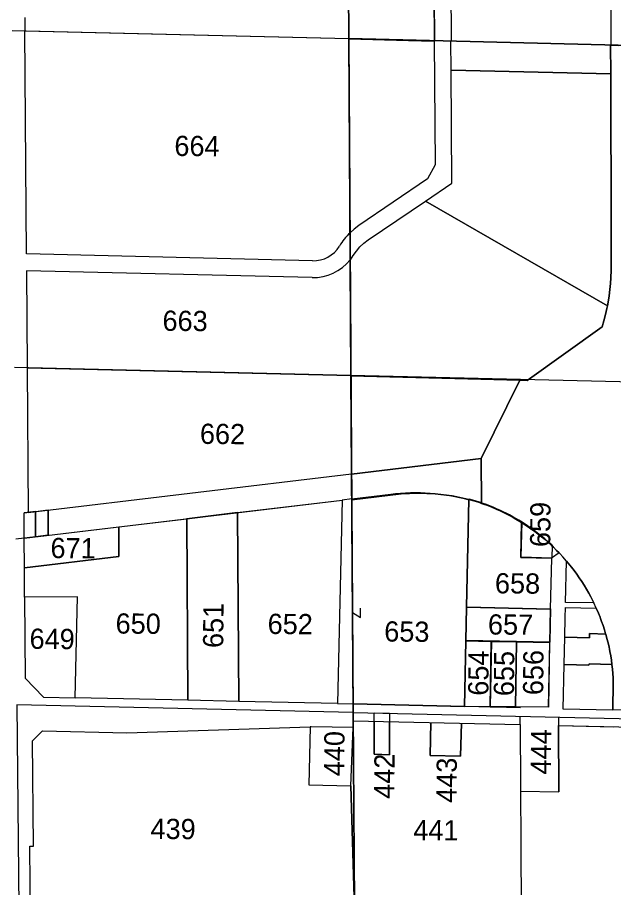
# Model space of a CAD drawing. Extents: x 582596 to 627039, y 145946 to 197316.
# Drawn here: x 604584 to 606930, y 174808 to 178233 of the extents above; entities that cross this region are included whole.
import ezdxf

# ---------------------------------------------------------------- set-up
doc = ezdxf.new("R2010")
doc.units = 0
for name, color, linetype in [('Defpoints 2', 7, 'Continuous'), ('E_RW_Existing', 7, 'Continuous'), ('E_RW_SixteenthLine', 7, 'Continuous'), ('P_MISC_NoPlot', 7, 'Continuous'), ('P_RW_PropertyConnector', 7, 'Continuous'), ('P_RW_PropertyLine', 7, 'Continuous'), ('P_RW_QuarterLine', 7, 'Continuous'), ('P_RW_SectionLine', 7, 'Continuous'), ('ROW', 7, 'Continuous')]:
    doc.layers.add(name, color=color, linetype=linetype)

msp = doc.modelspace()

# ---------------------------------------------------------------- linework, layer by layer
at = {"layer": 'E_RW_Existing'}
for p, q in [((606221.3, 178682.7), (606225.2, 178141.3)), ((605893.3, 177278.2), (605892.6, 177385)), ((605449.8, 176283.3), (605250, 176259.4))]:
    msp.add_line(p, q, dxfattribs=at)
at = {"layer": 'E_RW_SixteenthLine'}
for p, q in [((605887.7, 178149.4), (605904.6, 175497.2)), ((605896.2, 176823.3), (604572.4, 176854.1)), ((607220, 176792.5), (605896.2, 176823.3)), ((605904.6, 175497.2), (605923.5, 172850.3))]:
    msp.add_line(p, q, dxfattribs=at)
at = {"layer": 'P_MISC_NoPlot'}
for points in [[(606993.6, 160308.3), (600102.2, 147849.8), (582596.4, 147849.8), (584141, 197316), (605971.8, 196079.3), (609781.9, 181857.8), (607212.6, 178117.5), (605887.7, 178149.4), (605896.2, 176823.3), (605904.6, 175497.2), (605914.1, 174173.8), (605923.5, 172850.3), (605943, 171523.9), (604673.2, 170334), (604629.1, 170230.1), (604629.4, 170060), (605962, 170045), (605958.9, 168865.5), (605954.8, 167533.5), (604633.8, 167557.8), (604638.5, 164918.1), (606975.2, 164878.2), (606986.2, 162297)], [(606993.6, 160308.3), (600102.2, 147849.8), (582596.4, 147849.8), (584141, 197316), (605971.8, 196079.3), (609781.9, 181857.8), (607212.6, 178117.5), (605887.7, 178149.4), (605896.2, 176823.3), (605904.6, 175497.2), (605914.1, 174173.8), (605923.5, 172850.3), (605943, 171523.9), (604673.2, 170334), (604629.1, 170230.1), (604629.4, 170060), (605962, 170045), (605958.9, 168865.5), (605954.8, 167533.5), (604633.8, 167557.8), (604638.5, 164918.1), (606975.2, 164878.2), (606986.2, 162297)], [(606993.6, 160308.3), (600102.2, 147849.8), (582596.4, 147849.8), (584141, 197316), (605971.8, 196079.3), (609781.9, 181857.8), (607212.6, 178117.5), (605887.7, 178149.4), (605896.2, 176823.3), (605904.6, 175497.2), (605914.1, 174173.8), (605923.5, 172850.3), (605943, 171523.9), (604673.2, 170334), (604629.1, 170230.1), (604629.4, 170060), (605962, 170045), (605958.9, 168865.5), (605954.8, 167533.5), (604633.8, 167557.8), (604638.5, 164918.1), (606975.2, 164878.2), (606986.2, 162297)], [(606996.1, 159645.4), (606986.2, 162297), (606975.2, 164878.2), (604638.5, 164918.1), (604633.8, 167557.8), (605954.8, 167533.5), (605962, 170045), (604629.4, 170060), (604629.1, 170230.1), (604673.2, 170334), (605943, 171523.9), (605923.5, 172850.3), (605914.1, 174173.8), (605904.6, 175497.2), (605896.2, 176823.3), (605887.7, 178149.4), (607212.6, 178117.5), (607212.6, 178117.5), (627039.4, 170600.9), (626501.4, 158385.8), (609890.9, 158385.8), (607772.6, 159126.1)]]:
    msp.add_lwpolyline(points, close=True, dxfattribs=at)
at = {"layer": 'P_RW_PropertyConnector'}
for p, q in [((605902.1, 175890.3), (605934.3, 175871.1)), ((605904.4, 175889), (605904.4, 175889)), ((605934.3, 175871.1), (605934.3, 175906.8))]:
    msp.add_line(p, q, dxfattribs=at)
at = {"layer": 'P_RW_PropertyLine'}
for p, q in [((605887.7, 178147.9), (606123.4, 178142.3)), ((606123.4, 178142.3), (605887.7, 178147.9)), ((606123.4, 178142.3), (606223.7, 178139.8)), ((606223.7, 178139.8), (606123.4, 178142.3)), ((606223.7, 178141.3), (606223.7, 178139.8)), ((606223.7, 178139.8), (606227.2, 177653)), ((606223.7, 178139.8), (606223.7, 178139.8)), ((606286.8, 178138.3), (606286.8, 178139.8)), ((606289.3, 178138.3), (606286.8, 178138.3)), ((606290.1, 178025.1), (606289.3, 178138.3)), ((606917.6, 178124.6), (606917.6, 178123.1)), ((606917.6, 178123.1), (606917.6, 178124.6)), ((606917.6, 178123.1), (606918, 178123.1)), ((606918, 178123.1), (606917.6, 178123.1)), ((606918, 178123.1), (606918, 178123.1)), ((606918, 178123.1), (606918.5, 178010)), ((606947.5, 178122.4), (606918, 178123.1)), ((606918.5, 178010), (606918, 178123.1)), ((606918, 178123.1), (606918, 178123.1)), ((606918, 178123.1), (606947.5, 178122.4)), ((606918.5, 178010), (606290.1, 178025.1)), ((606293.4, 177580.4), (606290.1, 178025.1)), ((606290.1, 178025.1), (606918.5, 178010)), ((606918.5, 178010), (606920.9, 177374.7)), ((606920.9, 177374.7), (606918.5, 178010)), ((606227.2, 177653), (606197.9, 177597.1)), ((606197.9, 177597.1), (605927.6, 177413.4)), ((606189.2, 177509.7), (606293.4, 177580.4)), ((605964.3, 177356.9), (606189.2, 177509.7)), ((606905.4, 177097.4), (606189.2, 177509.7)), ((606189.2, 177509.7), (606905.4, 177097.4)), ((605908.7, 177399.4), (605892.6, 177385)), ((605927.6, 177413.4), (605908.7, 177399.4)), ((606920.9, 177374.7), (606919.9, 177235.7)), ((606919.9, 177235.7), (606920.9, 177374.7)), ((605917.6, 177312.7), (605931.6, 177329.1)), ((605931.6, 177329.1), (605947.2, 177343.9)), ((605947.2, 177343.9), (605964.3, 177356.9)), ((605894.3, 177278.4), (605905.5, 177294.9)), ((605905.5, 177294.9), (605917.6, 177312.7)), ((605893.3, 177277.7), (605894.3, 177278.4)), ((606919.9, 177235.7), (606919.1, 177210.8)), ((606919.1, 177210.8), (606919.9, 177235.7)), ((605743.6, 177208.6), (605743.6, 177208.6)), ((606918.9, 177208.2), (606917.6, 177185.9)), ((606917.6, 177185.9), (606918.9, 177208.2)), ((606919.1, 177210.8), (606918.9, 177208.2)), ((606918.9, 177208.2), (606919.1, 177210.8)), ((606915.2, 177161.1), (606912.1, 177136.4)), ((606912.1, 177136.4), (606915.2, 177161.1)), ((606917.6, 177185.9), (606915.2, 177161.1)), ((606915.2, 177161.1), (606917.6, 177185.9)), ((606912.1, 177136.4), (606908.2, 177111.7)), ((606908.2, 177111.7), (606912.1, 177136.4)), ((606903.4, 177087.3), (606897.9, 177062.9)), ((606897.9, 177062.9), (606903.4, 177087.3)), ((606905.4, 177097.4), (606903.4, 177087.3)), ((606903.4, 177087.3), (606905.4, 177097.4)), ((606908.2, 177111.7), (606905.4, 177097.4)), ((606905.4, 177097.4), (606908.2, 177111.7)), ((606897.9, 177062.9), (606891.7, 177038.8)), ((606891.7, 177038.8), (606897.9, 177062.9)), ((606891.7, 177038.8), (606884.6, 177014.9)), ((606884.6, 177014.9), (606891.7, 177038.8)), ((606884.6, 177014.9), (606589.4, 176803.8)), ((606589.4, 176803.8), (606884.6, 177014.9)), ((604622.4, 176852.9), (604626.5, 176284.4)), ((606560.5, 176804.5), (605896.2, 176821.9)), ((605896.2, 176821.9), (606560.5, 176804.5)), ((606560.5, 176804.5), (606408.8, 176496.3)), ((606408.8, 176496.3), (606560.5, 176804.5)), ((606589.4, 176803.8), (606560.5, 176804.5)), ((606560.5, 176804.5), (606589.4, 176803.8)), ((606408.8, 176496.3), (605898.7, 176435)), ((605898.7, 176435), (606408.8, 176496.3)), ((606410, 176320), (606408.8, 176496.3)), ((606408.8, 176496.3), (606410, 176320)), ((606093.9, 176357.2), (605899.3, 176333.9)), ((605899.3, 176333.9), (606093.9, 176357.2)), ((606052.7, 176355.4), (605899.3, 176337)), ((606160.9, 176360.5), (606093.9, 176357.2)), ((606093.9, 176357.2), (606160.9, 176360.5)), ((606228, 176357.9), (606160.9, 176360.5)), ((606160.9, 176360.5), (606228, 176357.9)), ((606294.5, 176349.5), (606228, 176357.9)), ((606228, 176357.9), (606294.5, 176349.5)), ((606360.1, 176335.3), (606294.5, 176349.5)), ((606294.5, 176349.5), (606360.1, 176335.3)), ((606360.1, 176335.3), (606350.7, 175911.1)), ((606350.7, 175911.1), (606360.1, 176335.3)), ((606385.3, 176328.1), (606360.1, 176335.3)), ((606360.1, 176335.3), (606385.3, 176328.1)), ((606402, 176322.7), (606385.3, 176328.1)), ((606385.3, 176328.1), (606402, 176322.7)), ((606410, 176320), (606402, 176322.7)), ((606402, 176322.7), (606410, 176320)), ((606418.6, 176317), (606410, 176320)), ((606410, 176320), (606418.6, 176317)), ((606435.1, 176310.9), (606418.6, 176317)), ((606418.6, 176317), (606435.1, 176310.9)), ((606451.4, 176304.5), (606435.1, 176310.9)), ((606435.1, 176310.9), (606451.4, 176304.5)), ((606467.5, 176297.7), (606451.4, 176304.5)), ((606451.4, 176304.5), (606467.5, 176297.7)), ((606483.5, 176290.5), (606467.5, 176297.7)), ((606467.5, 176297.7), (606483.5, 176290.5)), ((604654.4, 176287.8), (604609.5, 176282.4)), ((604610.2, 176182.8), (604609.5, 176282.4)), ((604655.1, 176188.2), (604654.4, 176287.8)), ((604705.1, 176194.1), (604704.4, 176293.8)), ((606499.3, 176282.9), (606483.5, 176290.5)), ((606483.5, 176290.5), (606499.3, 176282.9)), ((606515, 176275), (606499.3, 176282.9)), ((606499.3, 176282.9), (606515, 176275)), ((606530.5, 176266.7), (606515, 176275)), ((606515, 176275), (606530.5, 176266.7)), ((606545.7, 176258.1), (606530.5, 176266.7)), ((606530.5, 176266.7), (606545.7, 176258.1)), ((606568.1, 176244.5), (606545.7, 176258.1)), ((606545.7, 176258.1), (606568.1, 176244.5)), ((606568.1, 176244.5), (606565.1, 176106.3)), ((606565.1, 176106.3), (606568.1, 176244.5)), ((606590.3, 176230.2), (606568.1, 176244.5)), ((606568.1, 176244.5), (606590.3, 176230.2)), ((606604.7, 176220.2), (606590.3, 176230.2)), ((606590.3, 176230.2), (606604.7, 176220.2)), ((606618.9, 176209.9), (606604.7, 176220.2)), ((606604.7, 176220.2), (606618.9, 176209.9)), ((606632.9, 176199.3), (606618.9, 176209.9)), ((606618.9, 176209.9), (606632.9, 176199.3)), ((606646.6, 176188.3), (606632.9, 176199.3)), ((606632.9, 176199.3), (606646.6, 176188.3)), ((604610.2, 176182.8), (604577.2, 176178.8)), ((604655.1, 176188.2), (604610.2, 176182.8)), ((606660.1, 176177.1), (606646.6, 176188.3)), ((606646.6, 176188.3), (606660.1, 176177.1)), ((606673.3, 176165.5), (606660.1, 176177.1)), ((606660.1, 176177.1), (606673.3, 176165.5)), ((606686.2, 176153.5), (606673.3, 176165.5)), ((606673.3, 176165.5), (606686.2, 176153.5)), ((606715.5, 176124.6), (606685.1, 176103.7)), ((606693.3, 176147), (606686.2, 176153.5)), ((606686.2, 176153.5), (606693.3, 176147)), ((606687.7, 176154.8), (606686.6, 176104.8)), ((606705.7, 176134.7), (606693.3, 176147)), ((606693.3, 176147), (606705.7, 176134.7)), ((606715.5, 176124.6), (606705.7, 176134.7)), ((606705.7, 176134.7), (606715.5, 176124.6)), ((606718, 176122.1), (606715.5, 176124.6)), ((606565.1, 176106.3), (606685.1, 176103.7)), ((606685.1, 176103.7), (606565.1, 176106.3)), ((606685.1, 176103.7), (606680.6, 175903.7)), ((606729.9, 176109.2), (606718, 176122.1)), ((606744.9, 176092.2), (606729.9, 176109.2)), ((606741.3, 175930.3), (606744.9, 176092.2)), ((606763.9, 176069.1), (606744.9, 176092.2)), ((606744.9, 176092.2), (606763.9, 176069.1)), ((604611.8, 175950.8), (604611, 176065.8)), ((606774.6, 176055.2), (606763.9, 176069.1)), ((606763.9, 176069.1), (606774.6, 176055.2)), ((606785, 176041.1), (606774.6, 176055.2)), ((606774.6, 176055.2), (606785, 176041.1)), ((606795, 176026.7), (606785, 176041.1)), ((606785, 176041.1), (606795, 176026.7)), ((606804.8, 176012.1), (606795, 176026.7)), ((606795, 176026.7), (606804.8, 176012.1)), ((606814.1, 175997.3), (606804.8, 176012.1)), ((606804.8, 176012.1), (606814.1, 175997.3)), ((606823.2, 175982.3), (606814.1, 175997.3)), ((606814.1, 175997.3), (606823.2, 175982.3)), ((606831.9, 175967), (606823.2, 175982.3)), ((606823.2, 175982.3), (606831.9, 175967)), ((606840.3, 175951.6), (606831.9, 175967)), ((606831.9, 175967), (606840.3, 175951.6)), ((606852.2, 175927.9), (606741.3, 175930.3)), ((606852.2, 175927.9), (606840.3, 175951.6)), ((606840.3, 175951.6), (606852.2, 175927.9)), ((606861.7, 175907.7), (606852.2, 175927.9)), ((606350.7, 175911.1), (606347.8, 175779.1)), ((606347.8, 175779.1), (606350.7, 175911.1)), ((606350.7, 175911.1), (606680.6, 175903.7)), ((606680.6, 175903.7), (606350.7, 175911.1)), ((606680.6, 175903.7), (606677.7, 175771.7)), ((606739.9, 175870.4), (606740.8, 175910.3)), ((606740.8, 175910.3), (606861.7, 175907.7)), ((606870.1, 175888.2), (606861.7, 175907.7)), ((606861.7, 175907.7), (606870.1, 175888.2)), ((606876.7, 175871.9), (606870.1, 175888.2)), ((606870.1, 175888.2), (606876.7, 175871.9)), ((606738.2, 175793.4), (606739.9, 175870.4)), ((606878.4, 175867.3), (606876.7, 175871.9)), ((606876.7, 175871.9), (606878.4, 175867.3)), ((606882.9, 175855.5), (606878.4, 175867.3)), ((606878.4, 175867.3), (606882.9, 175855.5)), ((606888.7, 175838.9), (606882.9, 175855.5)), ((606882.9, 175855.5), (606888.7, 175838.9)), ((606894.1, 175822.3), (606888.7, 175838.9)), ((606888.7, 175838.9), (606894.1, 175822.3)), ((606898.7, 175806.8), (606894.1, 175822.3)), ((606894.1, 175822.3), (606898.7, 175806.8)), ((606735.8, 175685.4), (606738.2, 175793.4)), ((606835.4, 175791.2), (606738.2, 175793.4)), ((606738.2, 175793.4), (606835.4, 175791.2)), ((606835.8, 175808.2), (606835.4, 175791.2)), ((606835.4, 175791.2), (606835.8, 175808.2)), ((606899.1, 175805.5), (606835.8, 175808.2)), ((606835.8, 175808.2), (606899.1, 175805.5)), ((606899.1, 175805.5), (606898.7, 175806.8)), ((606898.7, 175806.8), (606899.1, 175805.5)), ((606903.8, 175788.6), (606899.1, 175805.5)), ((606899.1, 175805.5), (606903.8, 175788.6)), ((606908.1, 175771.5), (606903.8, 175788.6)), ((606903.8, 175788.6), (606908.1, 175771.5)), ((606347.8, 175779.1), (606343.6, 175520.3)), ((606343.6, 175520.3), (606347.8, 175779.1)), ((606347.8, 175779.1), (606447.9, 175776.8)), ((606447.9, 175776.8), (606347.8, 175779.1)), ((606447.9, 175776.8), (606443.6, 175519.6)), ((606443.6, 175519.6), (606447.9, 175776.8)), ((606447.9, 175776.8), (606547.8, 175774.6)), ((606547.8, 175774.6), (606447.9, 175776.8)), ((606547.8, 175774.6), (606543.6, 175518.9)), ((606543.6, 175518.9), (606547.8, 175774.6)), ((606547.8, 175774.6), (606677.7, 175771.7)), ((606677.7, 175771.7), (606547.8, 175774.6)), ((606673.6, 175517.9), (606679.3, 175772.9)), ((606677.7, 175771.7), (606673.6, 175517.9)), ((606912, 175754.4), (606908.1, 175771.5)), ((606908.1, 175771.5), (606912, 175754.4)), ((606913.6, 175746.4), (606912, 175754.4)), ((606912, 175754.4), (606913.6, 175746.4)), ((606915.4, 175737.3), (606913.6, 175746.4)), ((606913.6, 175746.4), (606915.4, 175737.3)), ((606918.6, 175720), (606915.4, 175737.3)), ((606915.4, 175737.3), (606918.6, 175720)), ((606921.3, 175702.7), (606918.6, 175720)), ((606918.6, 175720), (606921.3, 175702.7)), ((606732, 175510.4), (606735.8, 175685.4)), ((606833.1, 175683.2), (606735.8, 175685.4)), ((606735.8, 175685.4), (606833.1, 175683.2)), ((606833.2, 175688.2), (606833.1, 175683.2)), ((606833.1, 175683.2), (606833.2, 175688.2)), ((606923.5, 175686.2), (606833.2, 175688.2)), ((606833.2, 175688.2), (606923.5, 175686.2)), ((606923.5, 175686.2), (606921.3, 175702.7)), ((606921.3, 175702.7), (606923.5, 175686.2)), ((606923.6, 175685.3), (606923.5, 175686.2)), ((606923.5, 175686.2), (606923.6, 175685.3)), ((606925.5, 175667.8), (606923.6, 175685.3)), ((606923.6, 175685.3), (606925.5, 175667.8)), ((606927, 175650.4), (606925.5, 175667.8)), ((606925.5, 175667.8), (606927, 175650.4)), ((606928.1, 175632.9), (606927, 175650.4)), ((606927, 175650.4), (606928.1, 175632.9)), ((606926.4, 175506.1), (606928.8, 175615.3)), ((606928.8, 175615.3), (606926.4, 175506.1)), ((606928.4, 175626.1), (606928.1, 175632.9)), ((606928.1, 175632.9), (606928.4, 175626.1)), ((606928.8, 175615.3), (606928.4, 175626.1)), ((606928.4, 175626.1), (606928.8, 175615.3)), ((606563.5, 175515.4), (605904.4, 175530.2)), ((606343.6, 175520.3), (605904.4, 175530.2)), ((606443.6, 175519.6), (606343.6, 175520.3)), ((606673.6, 175517.9), (606343.6, 175520.3)), ((606543.6, 175518.9), (606443.6, 175519.6)), ((606673.6, 175517.9), (606543.6, 175518.9)), ((606926.4, 175506.1), (606732, 175510.4)), ((607029.2, 175508.8), (606926.4, 175506.1)), ((605987.5, 175462.3), (605987.4, 175495.3)), ((605987.4, 175495.3), (606047.4, 175494)), ((606047.4, 175494), (606047.5, 175461)), ((606562.7, 175449.4), (606562.5, 175482.4)), ((606712.5, 175479.1), (606712.7, 175446)), ((605904.9, 175464.2), (606562, 175449.4)), ((605987.7, 175332.1), (605987.5, 175462.3)), ((605987.5, 175462.3), (605987.7, 175332.1)), ((606047.5, 175461), (606047.7, 175330.7)), ((606047.7, 175330.7), (606047.5, 175461)), ((606207.9, 175327.3), (606210.8, 175457.3)), ((606210.8, 175457.3), (606207.9, 175327.3)), ((606330.8, 175454.6), (606327.9, 175324.6)), ((606327.9, 175324.6), (606330.8, 175454.6)), ((606562.7, 175449.4), (606566.4, 174710)), ((606712.7, 175446), (606931.2, 175440)), ((606712.7, 175446), (606714, 175184.1)), ((606712.7, 175446), (607226.6, 175434.5)), ((606714, 175184.1), (606712.7, 175446)), ((606047.7, 175330.7), (605987.7, 175332.1)), ((605987.7, 175332.1), (606047.7, 175330.7)), ((606327.9, 175324.6), (606207.9, 175327.3)), ((606207.9, 175327.3), (606327.9, 175324.6)), ((606564, 175187.4), (606714, 175184.1))]:
    msp.add_line(p, q, dxfattribs=at)
for points in [[(606919.9, 178124.5), (606917.5, 178783), (606286.4, 178798.9), (606291.2, 178139.7)], [(605887.7, 178149.4), (605883.4, 178743), (604956.1, 178766.4), (604840, 178682.2)], [(606225.2, 178141.3), (606221.3, 178682.7), (606169.1, 178735.8), (605883.4, 178743), (605887.7, 178149.4)], [(604612.5, 178232.7), (604612.9, 178180.1), (605887.7, 178149.4)], [(605745.2, 177274.6), (604619.2, 177301.7), (604612.9, 178180.1), (605887.7, 178149.4)], [(605887.7, 178149.4), (606225.2, 178141.3)], [(605887.7, 178149.4), (606225.2, 178141.3)], [(605896.2, 176823.3), (605893.3, 177278.2)], [(605893.3, 177278.2), (605896.2, 176823.3)], [(605743.6, 177208.6), (604619.6, 177235.6), (604622.4, 176852.9), (605896.2, 176823.3)], [(605899.3, 176337.1), (605861.5, 176332.5), (605843.7, 175531.6)], [(605904.4, 175530.2), (606343.6, 175520.3), (606361.7, 176336.5)], [(604611.1, 176065.8), (604983, 176110.3), (604982.2, 176227.3), (605250, 176259.4), (605254.5, 175544.8), (604811, 175554.8), (604819.9, 175952.3), (604611.9, 175950.8)], [(605250, 176259.4), (605254.5, 175544.8)], [(606352.3, 175912.3), (606682.2, 175904.8), (606686.6, 176104.8), (606566.7, 176107.5), (606569.7, 176245.7)], [(606682.2, 175904.8), (606679.3, 175772.9), (606349.3, 175780.3)], [(606449.3, 175778), (606443.6, 175519.6), (606543.6, 175518.9), (606549.3, 175775.8)], [(605843.7, 175531.6), (605904.4, 175530.2)], [(605910.7, 174642.8), (604634.8, 174671.5), (604632, 174970.2), (604647, 174970.3), (604643.2, 175385.6), (604682.7, 175424.6), (605014.6, 175417.2), (605735.3, 175440.7), (605730.3, 175212.3), (605895.2, 175208.6), (605910.1, 174724.7), (605910.7, 174642.8)], [(605910.1, 174724.7), (605895.2, 175208.6), (605905, 175437.2), (605905, 175437.2), (605904.8, 175464.2), (605904.9, 175464.2)]]:
    msp.add_lwpolyline(points, dxfattribs=at)
for points in [[(605449.8, 176283.3), (605861.5, 176332.5), (605843.7, 175531.6), (605454.5, 175540.3)], [(604610.2, 176182.8), (604609.5, 176282.4), (604654.4, 176287.8), (604655.1, 176188.2)], [(604654.4, 176287.8), (604704.4, 176293.8), (604705.1, 176194.1), (604655.1, 176188.2)], [(605250, 176259.4), (605449.8, 176283.3), (605454.5, 175540.3), (605254.5, 175544.8)], [(604982.2, 176227.3), (604983, 176110.3), (604611.1, 176065.8), (604610.2, 176182.8)], [(604611.9, 175950.8), (604614.1, 175632.1), (604686.4, 175557.6), (604811, 175554.8), (604819.9, 175952.3)], [(605735.3, 175440.7), (605730.3, 175212.3), (605895.2, 175208.6), (605905, 175437.2), (605740, 175440.9)]]:
    msp.add_lwpolyline(points, close=True, dxfattribs=at)
for centre, radius, start, end in [((606078.4, 177194.8), 266, 134.3136, 148.8406), ((605748.1, 177394.5), 120, 268.6208, 328.8525), ((605748.1, 177394.5), 186, 268.6208, 321.3048), ((606148.7, 175552.4), 808.7, 74.7375, 96.8193), ((606161.6, 175594), 769, 57.9464, 74.9189), ((606161.6, 175594), 769, 46.8297, 57.9464)]:
    msp.add_arc(centre, radius, start, end, dxfattribs=at)
at = {"layer": 'P_RW_QuarterLine'}
msp.add_line((605887.7, 178149.4), (607212.6, 178117.5), dxfattribs=at)
at = {"layer": 'P_RW_SectionLine'}
for p, q in [((604562.9, 178181.3), (605887.7, 178149.4)), ((605887.7, 178149.4), (607212.6, 178117.5)), ((605904.6, 175497.2), (604581.9, 175526.9)), ((604581.9, 175526.9), (604606.3, 172875.4)), ((605904.6, 175497.2), (607227.4, 175467.5))]:
    msp.add_line(p, q, dxfattribs=at)
at = {"layer": 'ROW'}
for p, q in [((604626.5, 176284.4), (605898.6, 176436.7)), ((604610.2, 176182.8), (605861.5, 176332.5))]:
    msp.add_line(p, q, dxfattribs=at)

# ---------------------------------------------------------------- texts
at = {"layer": 'Defpoints 2'}
for s, rotation, p in [('664', 359.5042, (605201.1, 177687.4)), ('663', 359.5042, (605154.4, 176999.2)), ('662', 359.5042, (605301.7, 176554.1)), ('659', 89.5042, (606680.6, 176147.7)), ('671', 359.5042, (604713.5, 176104.6)), ('658', 359.5042, (606462.8, 175965.8)), ('651', 89.5042, (605393.5, 175750.4)), ('650', 359.5042, (604969.8, 175807.5)), ('652', 359.5042, (605568.2, 175806)), ('653', 359.5042, (606027.1, 175776.1)), ('657', 359.5042, (606435.3, 175803.7)), ('649', 359.5042, (604631.1, 175747.4)), ('654', 89.5042, (606437.1, 175562.6)), ('655', 89.5042, (606537.8, 175560.9)), ('656', 89.5042, (606652.9, 175564.8)), ('440', 89.5042, (605869.8, 175245.6)), ('444', 89.5042, (606683.1, 175252.4)), ('442', 89.5042, (606066.8, 175156.7)), ('443', 89.5042, (606311.9, 175140.9)), ('439', 359.5042, (605107.2, 174999.3)), ('441', 359.5042, (606141.7, 174994.5))]:
    msp.add_text(s, height=79.68, rotation=rotation, dxfattribs=at).set_placement(p)

doc.saveas('drawing.dxf')
